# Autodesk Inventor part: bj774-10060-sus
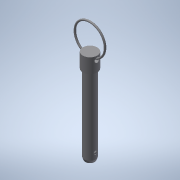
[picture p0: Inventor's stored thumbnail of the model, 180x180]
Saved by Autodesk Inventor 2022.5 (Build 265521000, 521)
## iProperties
Created: 2016-12
Part Number: bj774-10060-sus
Material: 一般
Document SubType Name: Modeling
Designer: imaocorp
Density: 1 g/cm^3
Appearance: 既定
Author: imaocorp
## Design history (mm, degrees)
node "bj774-10060-sus.x_t1"
node "bj774-10060-sus"
node "Base1"
